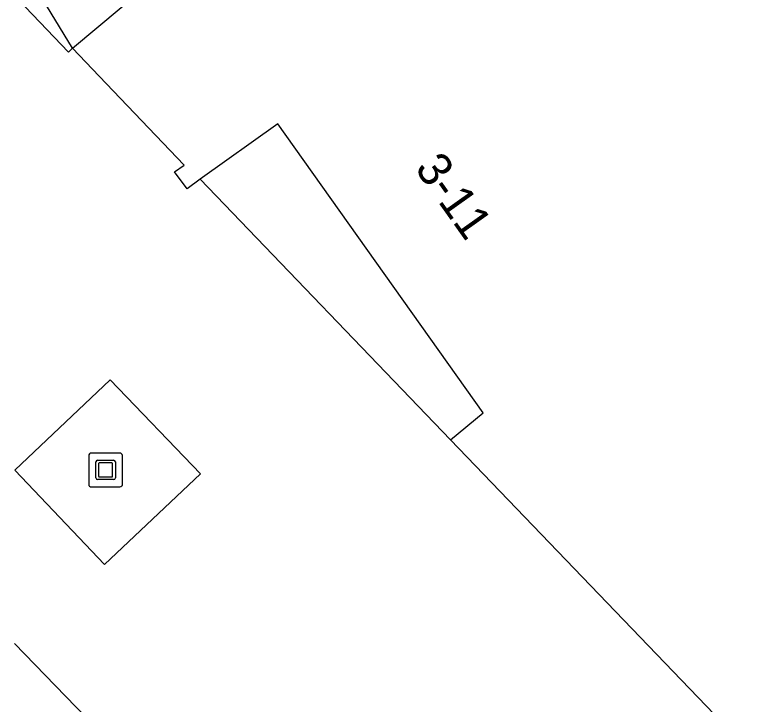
# Model space of a CAD drawing. Extents: x 161087 to 161922, y 382574 to 383873.
# Drawn here: x 161213.18 to 161234.98, y 383184.3 to 383204.67 of the extents above; entities that cross this region are included whole.
import ezdxf

# ---------------------------------------------------------------- set-up
doc = ezdxf.new("R2010")
doc.units = 0
for name, color, linetype in [('IMGEO_Fietspad_gesloten', 7, 'Continuous'), ('IMGEO_Kunstobject', 7, 'Continuous'), ('IMGEO_Pand', 7, 'Continuous'), ('IMGEO_Pand_nummerreeks', 7, 'Continuous'), ('IMGEO_Pand_overbouw', 7, 'Continuous'), ('IMGEO_Voetgangersgebied_open', 7, 'Continuous')]:
    doc.layers.add(name, color=color, linetype=linetype)

msp = doc.modelspace()

# ---------------------------------------------------------------- linework, layer by layer
at = {"layer": 'IMGEO_Fietspad_gesloten'}
msp.add_lwpolyline([(161213.179, 383186.09), (161222.243, 383176.723), (161234.788, 383163.737)], dxfattribs=at)
at = {"layer": 'IMGEO_Kunstobject'}
for p, q in [((161216.283, 383191.72), (161215.442, 383191.72)), ((161216.283, 383191.72), (161215.442, 383191.72)), ((161215.367, 383191.636), (161215.367, 383190.795)), ((161215.367, 383191.636), (161215.367, 383190.795)), ((161215.581, 383190.984), (161215.581, 383191.458)), ((161215.631, 383191.508), (161216.105, 383191.508)), ((161216.155, 383191.458), (161216.155, 383190.984)), ((161216.367, 383190.804), (161216.367, 383191.645)), ((161216.367, 383190.804), (161216.367, 383191.645)), ((161215.661, 383191.408), (161215.661, 383191.034)), ((161216.055, 383191.428), (161215.681, 383191.428)), ((161216.075, 383191.034), (161216.075, 383191.408)), ((161216.105, 383190.934), (161215.631, 383190.934)), ((161215.681, 383191.014), (161216.055, 383191.014)), ((161215.451, 383190.72), (161216.292, 383190.72)), ((161215.451, 383190.72), (161216.292, 383190.72))]:
    msp.add_line(p, q, dxfattribs=at)
for centre, radius, start, end in [((161215.445, 383191.642), 0.0779, 92.4484, 184.2845), ((161215.445, 383191.642), 0.0779, 92.4484, 184.2845), ((161216.289, 383191.642), 0.0779, 2.4484, 94.2845), ((161216.289, 383191.642), 0.0779, 2.4484, 94.2845), ((161215.631, 383191.458), 0.05, 90, 180), ((161216.105, 383191.458), 0.05, 360, 90), ((161215.681, 383191.408), 0.02, 90, 180), ((161216.055, 383191.408), 0.02, 360, 90), ((161215.681, 383191.034), 0.02, 180, 270), ((161216.055, 383191.034), 0.02, 270, 0), ((161215.631, 383190.984), 0.05, 180, 270), ((161216.105, 383190.984), 0.05, 270, 0), ((161216.289, 383190.798), 0.0779, 272.4484, 4.2845), ((161216.289, 383190.798), 0.0779, 272.4484, 4.2845), ((161215.445, 383190.798), 0.0779, 182.4484, 274.2845), ((161215.445, 383190.798), 0.0779, 182.4484, 274.2845)]:
    msp.add_arc(centre, radius, start, end, dxfattribs=at)
at = {"layer": 'IMGEO_Pand'}
for points in [[(161214.888, 383203.681), (161228.197, 383214.816), (161227.113, 383216.127), (161229.277, 383217.916), (161229.145, 383218.076)], [(161247.047, 383173.276), (161243.848, 383173.6), (161226.063, 383192.108), (161227.023, 383192.911), (161220.954, 383201.444), (161218.664, 383199.808), (161218.273, 383199.528), (161217.903, 383200.032), (161218.189, 383200.227), (161215.678, 383202.854), (161214.888, 383203.681)]]:
    msp.add_lwpolyline(points, dxfattribs=at)
at = {"layer": 'IMGEO_Pand_overbouw'}
for points in [[(161215.723, 383227.077), (161203.936, 383214.907), (161214.772, 383203.57), (161214.888, 383203.681), (161226.816, 383213.661)], [(161226.063, 383192.108), (161227.023, 383192.911), (161220.954, 383201.444), (161218.664, 383199.808)]]:
    msp.add_lwpolyline(points, close=True, dxfattribs=at)
at = {"layer": 'IMGEO_Voetgangersgebied_open'}
for points in [[(161214.888, 383203.681), (161213.87, 383205.356)], [(161215.835, 383188.423), (161213.186, 383191.21), (161215.998, 383193.88), (161218.667, 383191.109), (161215.835, 383188.423)]]:
    msp.add_lwpolyline(points, dxfattribs=at)

# ---------------------------------------------------------------- texts
at = {"layer": 'IMGEO_Pand_nummerreeks'}
msp.add_text('3-11', height=1, rotation=305.42, dxfattribs=at).set_placement((161224.982, 383200.128))

doc.saveas('drawing.dxf')
